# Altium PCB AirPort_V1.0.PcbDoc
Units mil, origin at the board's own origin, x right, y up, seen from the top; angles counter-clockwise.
Board outline 2235 x 1330 mil, 2 copper layers (Top Layer, Bottom Layer); 46 components, 18 nets, 126 pads, 46 vias.
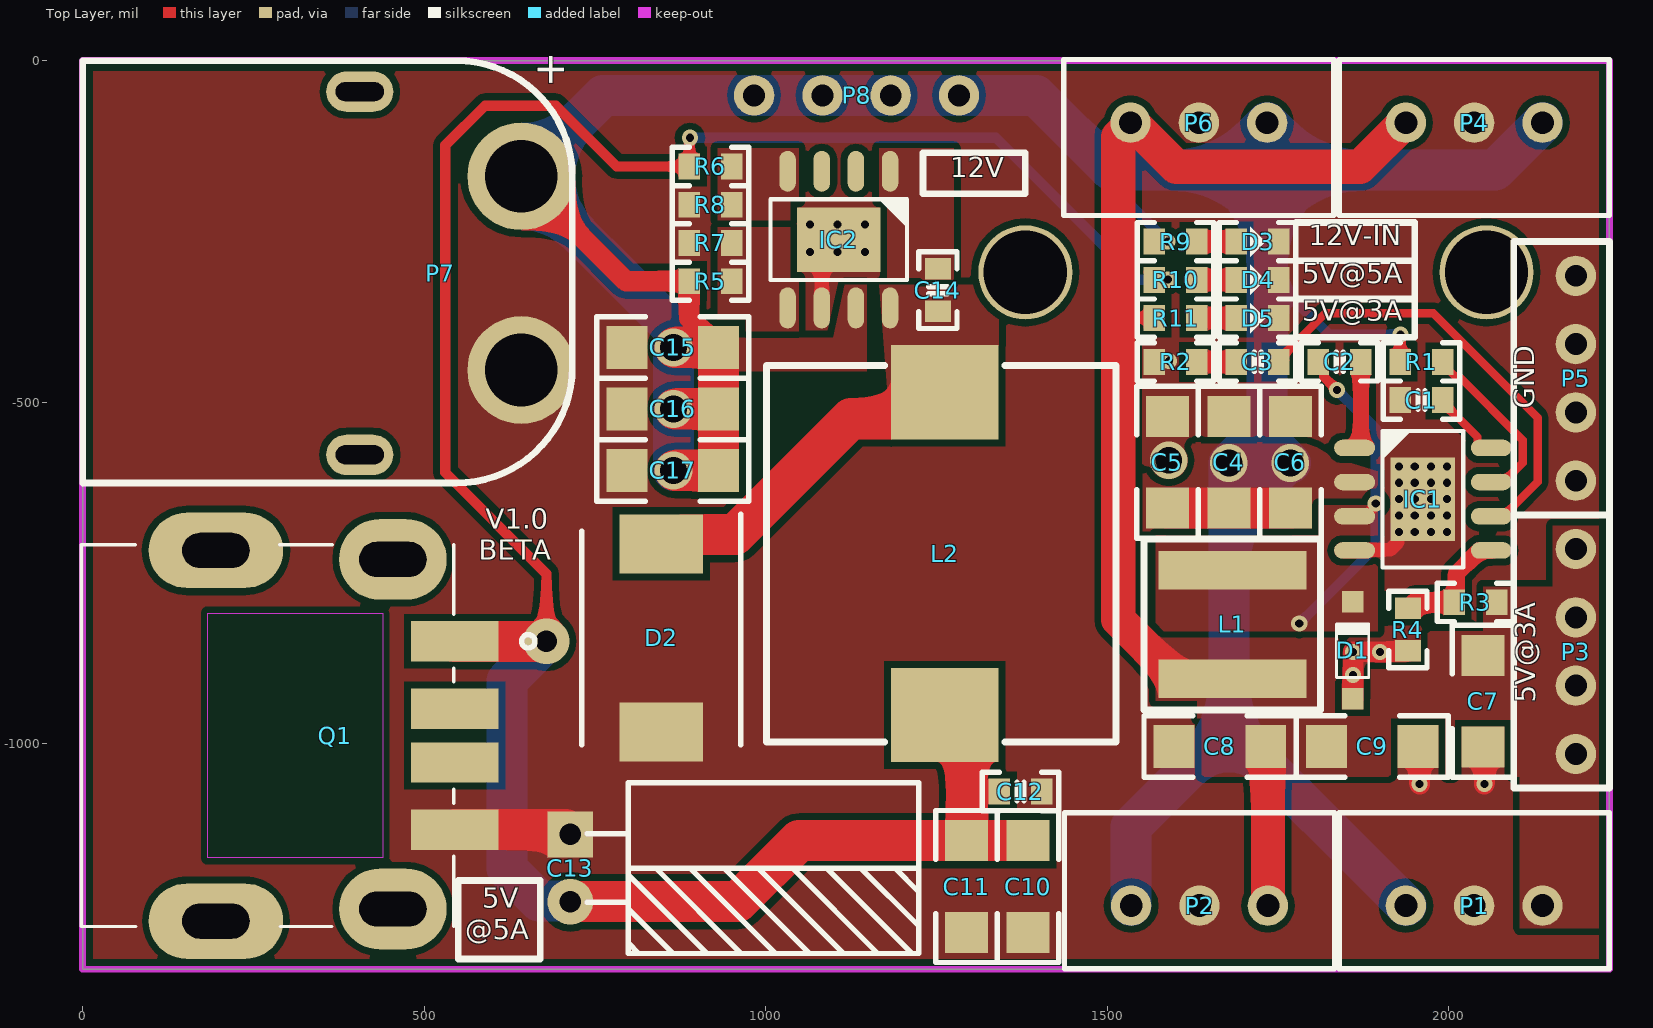
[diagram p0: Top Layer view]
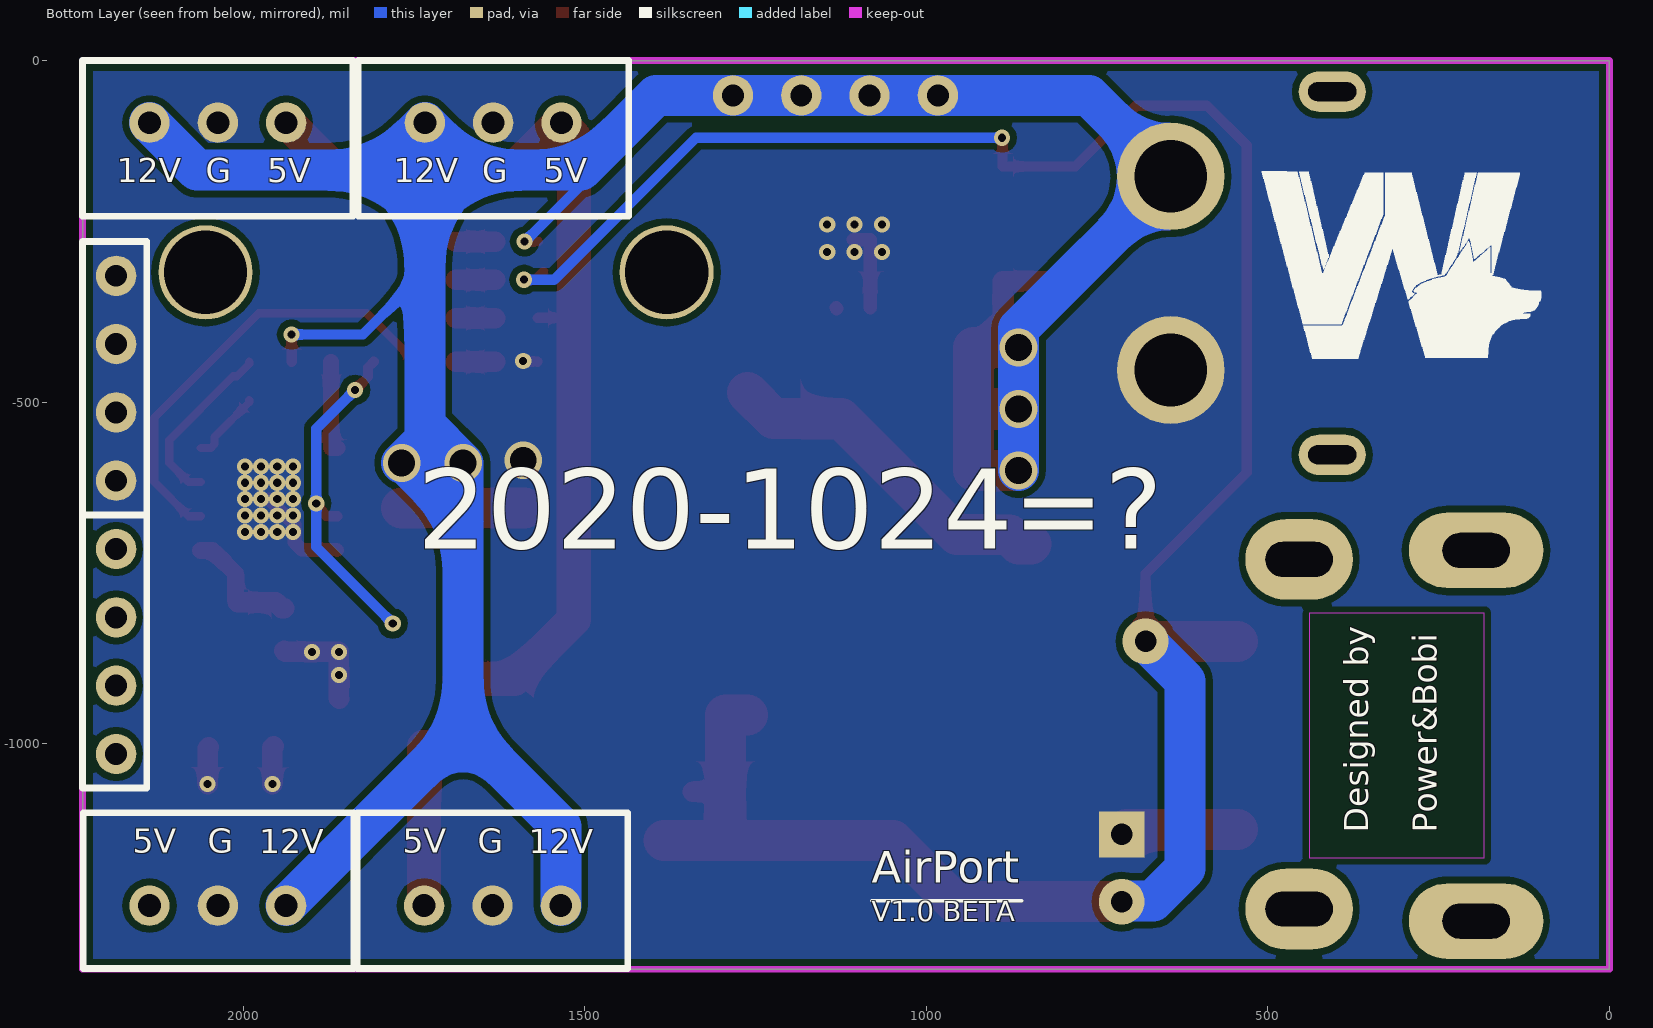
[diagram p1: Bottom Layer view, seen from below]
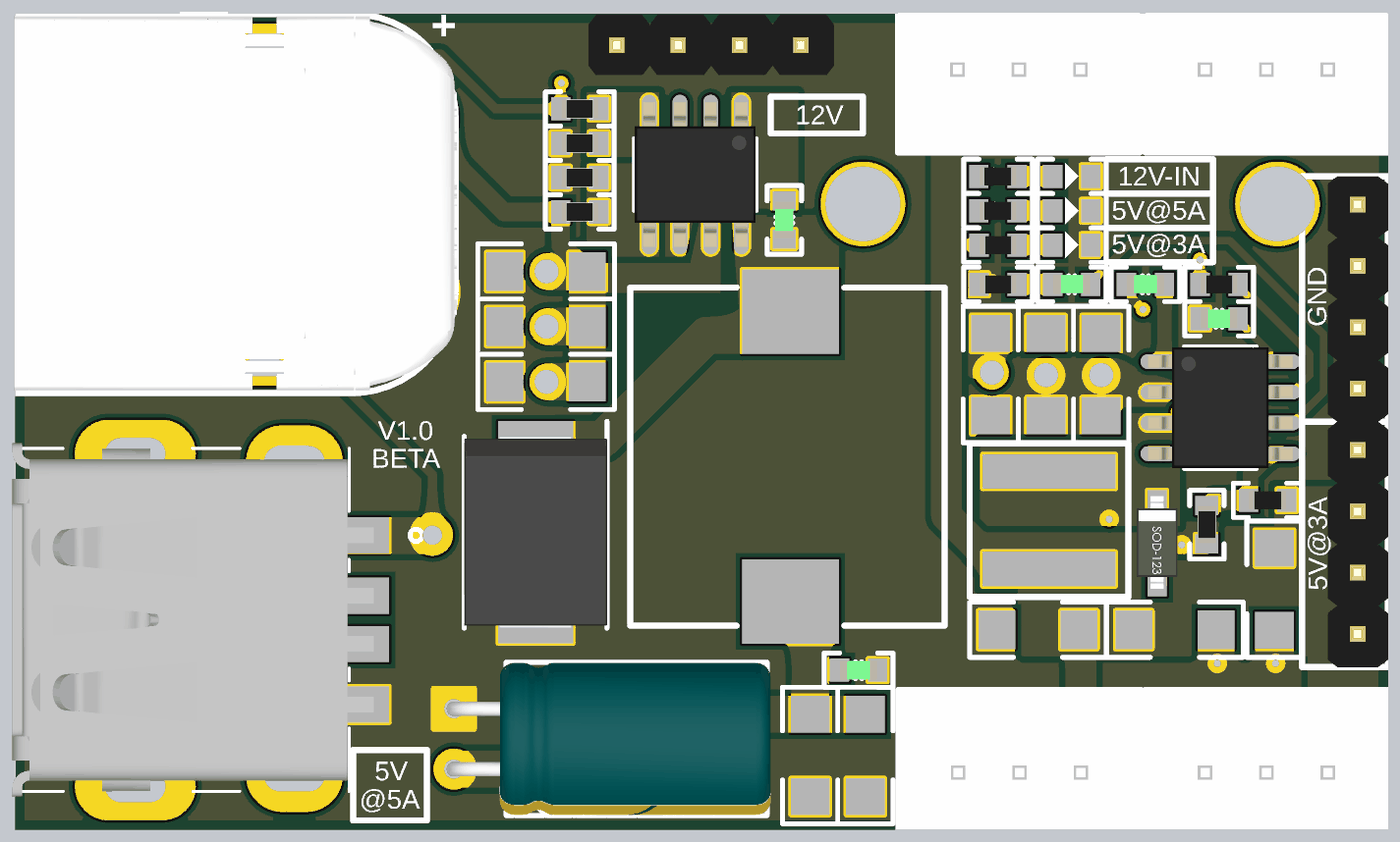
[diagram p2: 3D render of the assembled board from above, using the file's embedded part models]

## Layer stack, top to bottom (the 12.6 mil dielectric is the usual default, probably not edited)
Top Solder: solder mask 0.4, Solder Resist, Dk 3.5
Top Layer: signal copper 1.4
Dielectric 1: dielectric 12.6, FR-4, Dk 4.8
Bottom Layer: signal copper 1.4
Bottom Solder: solder mask 0.4, Solder Resist, Dk 3.5

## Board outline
0,-1330 0,0 2235,0 2235,-1330

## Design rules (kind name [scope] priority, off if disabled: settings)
Clearance [All] p1: gap=10 ignorepadtopadclearanceinfootprint=FALSE except(0: Arc-Hole Track-Hole SMDPad-Hole THPad-Hole Via-Hole Fill-Hole Poly-Hole Region-Hole Text-Hole)
PlaneConnect [All] p1: planeconnectstyle=Direct reliefexpansion=20 reliefentries=4 reliefconductorwidth=10 reliefairgap=10
PolygonConnect [All] p1: connectstyle=Direct reliefconductorwidth=10 reliefentries=4 polygonreliefangle="90 Angle" airgapwidth=10
RoutingVias [All] p1: holewidth=11.81 width=23.62 viastyle="Through Hole" minholewidth=11.81 minwidth=23.62 maxholewidth=11.81 maxwidth=23.62
SolderMaskExpansion [All] p1: expansion=4 istentingtop=FALSE
Width [All] p1: maxlimit=100 minlimit=10 preferedwidth=15
29 further rules are at their usual default settings.

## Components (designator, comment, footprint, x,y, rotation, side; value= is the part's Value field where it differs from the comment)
C1 "100nF" CAP-0603 1959.9,-497 r0 top
C2 "10nF" CAP-0603 1840,-441 r0 top
C3 "6.8nF" CAP-0603 1720,-441 r0 top
C4 "10uF" CAP-1206 1678,-588.07 r270 top
C5 "10uF" CAP-1206 1588,-588.07 r270 top
C6 "10uF" CAP-1206 1768,-588.07 r270 top
C7 "10uF" CAP-1206 2050,-937.93 r90 top
C8 "10uF" CAP-1206 1665,-1004 r0 top
C9 "10uF" CAP-1206 1887.93,-1004 r180 top
C10 "10uF" CAP-1206 1384,-1208.93 r90 top
C11 "10uF" CAP-1206 1294,-1208.93 r90 top
C12 "0.01uF" CAP-0603 1372.9,-1070 r180 top
C13 "100nF" "CAP-2.5*6.3*11.2-H - GD" 714,-1182 r270 top
C14 "0.01uF" CAP-0603 1252,-336.13 r90 top
C15 "4.7uF" CAP-1206 864,-420 r0 top
C16 "4.7uF" CAP-1206 864,-510 r0 top
C17 "0.01uF" CAP-1206 864,-600 r0 top
D1 "SS14" SOD_123 1859,-863 r270 top
D2 "SS14" DO-214AB 847,-845.2 r270 top
D3 "RED" LED-0603 1720,-265 r0 top
D4 "RED" LED-0603 1720.1,-321 r0 top
D5 "RED" LED-0603 1720,-377 r0 top
IC1 "MP1484" SOIC_8_PAD 1962,-642 r270 top
IC2 "TPS5450DDA" SOIC_8_PAD 1107,-262.06 r180 top
L1 "10uH 5A" XAL6060-103MEB 1683,-825.47 r90 top
L2 "15uH" SMD-13.45x12.6x4.8mm 1271.83,-720.78 r270 top
P1 "XH-3AW" XH_3 2037,-1237 r0 top
P2 "XH-3AW" XH_3 1635,-1237 r0 top
P3 "HDR1x4_2.54" HDR1x4_2.54_180 2185.82,-715 r0 top
P4 "XH-3AW" XH_3 2037,-91 r180 top
P5 "HDR1x4_2.54" HDR1x4_2.54_180 2185.82,-315 r0 top
P6 "XH-3AW" XH_3 1634,-91 r180 top
P7 "XT60PW-M" XT60PW-M 642,-453 r90 top
P8 "HDR1x4_2.54" HDR1x4_2.54_180 983,-51 r90 top
Q1 "USB A" USB_A_MALE_4_POS_Solder_RA_SMD_4_Terminal_1_Port 455.27,-988 r270 top
R1 "100K" R-0603 1959.9,-441 r180 top
R2 "6.8K" R-0603 1600,-441 r180 top
R3 "44.2K" R-0603 2038.9,-793 r0 top
R4 "10K" R-0603 1940,-832.9 r90 top
R5 "15K" R-0603 918.9,-323 r180 top
R6 "10K" R-0603 919,-155 r0 top
R7 "10K" R-0603 918.9,-267 r180 top
R8 "3.16K" R-0603 918.9,-211 r0 top
R9 "10k" R-0603 1599.9,-265 r180 top
R10 "10k" R-0603 1599.9,-321 r180 top
R11 "10k" R-0603 1600,-377 r180 top

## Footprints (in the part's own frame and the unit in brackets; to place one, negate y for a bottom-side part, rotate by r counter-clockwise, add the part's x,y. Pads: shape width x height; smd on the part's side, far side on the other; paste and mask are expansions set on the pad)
"CAP-2.5*6.3*11.2-H - GD" [mm] "脚距2.5mm直径6.3mm高度11.2mm"
  rect 1.7x1.7 hole 0.8: 1(-1.25,0)
  round 1.7 hole 0.8: 2(1.25,0)
  silkscreen extent -3.18,0.63 3.17,12.95, body extent -3.15,-0.3 3.16,13.11, height 6.32
CAP-0603 [mm]
  rect 0.8x0.96 smd: 1(-0.79,0) 2(0.79,0)
  silkscreen extent -1.42,-0.71 1.42,0.71, body extent -0.76,-0.39 0.76,0.39, height 0.9
CAP-1206 [mm] "贴片元件"
  rect 1.524x1.6 smd: 1(-1.703,0) 2(1.7,0)
  silkscreen extent -2.83,-1.14 2.83,1.14, body extent -1.91,-0.89 1.91,0.89, height 1
DO-214AB [mm]
  rect 2.2x3.1 smd: 1(3.5,0) 2(-3.5,0)
  silkscreen extent -4.6,-2.95 3.97,2.95, body extent -3.97,-2.95 3.97,2.95, height 2.5
HDR1x4_2.54_180 [mm]
  round 1.5 hole 0.813: 1(0,0) 2(0,-2.54) 3(0,-5.08) 4(0,-7.62)
  body extent -1.25,-8.89 1.25,1.27, height 8.2
LED-0603 [mm]
  rect 0.8x0.96 smd: 1(-0.79,0) 2(0.79,0)
  silkscreen extent -1.42,-0.71 1.42,0.71, body extent -0.81,-0.4 0.81,0.4, height 0.6
R-0603 [mm]
  rect 0.8x0.96 smd: 1(-0.79,0) 2(0.79,0)
  silkscreen extent -1.42,-0.71 1.42,0.71, body extent -0.76,-0.38 0.76,0.38, height 0.41
SMD-13.45x12.6x4.8mm [mm]
  rect 3.5x4 smd: 1(-5.975,-0.25) 2(6.025,-0.25)
  silkscreen extent -6.98,-6.88 7.03,6.12, body extent -6.96,-6.88 7.01,6.08, height 5
SOD_123 [mm]
  rect 0.8x0.8 smd: 1(1.8,0) 2(-1.8,0)
  silkscreen extent -1.02,-0.6 1.02,0.6, body extent -1.95,-0.85 1.9,0.85, height 1.42
SOIC_8_PAD [mil]
  oval 24x60 smd: 1(-75,-100) 2(-25,-100) 3(25,-100) 4(75,-100) 5(75,100) 6(25,100) 7(-25,100) 8(-75,100)
  rect 122.05x94.49 smd: 9(0,0)
  silkscreen extent -100,-59 100,59, body extent -98,-118 98,118, height 71
USB_A_MALE_4_POS_Solder_RA_SMD_4_Terminal_1_Port [mm] "能过5A大电流：https://item.taobao.com/item.htm?spm=a1z0d.6639537.1997196601.4.56bb7484TiP584&id=575662474806"
  rect 1.5x3.25 smd: 1(-3.5,2.27) 2(-1,2.27) 3(1,2.27) 4(3.5,2.27)
  oval 2.8x5 hole 1.3 slot 2.5 at 90 deg: ""(-6.883,-6.604) ""(6.9,-6.604)
  oval 3x4 hole 1.3 slot 2.5 at 90 deg: ""(-6.55,-0.025) ""(6.45,-0.025)
  Keep-Out Layer region: 4.55,-6.914 -4.553,-6.914 -4.553,-0.41 4.55,-0.41
  silkscreen extent -7.1,-11.61 7.1,5.26, body extent -7.32,-11.68 7.31,3.26, height 7.63
XAL6060-103MEB [mm]
  rect 1.43x5.5 smd: 1(-2.02,0) 2(2.02,0)
  silkscreen extent -3.18,-3.28 3.18,3.28, body extent -2.84,-2.84 2.84,2.84, height 2.03
XH_3 [mm]
  round 1.5 hole 0.85: 1(-2.54,0) 2(0,0) 3(2.54,0)
  silkscreen extent -5.02,-2.35 5.02,3.45, body extent -5.02,-2.35 5.02,3.45, height 7.21
XT60PW-M [mm]
  oval 1.5x2.5 hole 0.7 slot 1.8 at 90 deg: 0(-3.15,6) 0(10.35,6)
  round 4 hole 2.7: 1(7.2,0) 2(0,0)
  silkscreen extent -4.2,-1.9 11.5,16.3, body extent -4.3,-1.95 11.6,16.35, height 8.45

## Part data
C1 C2 C3 C4 C5 C6 C7 C8 C9 C10 C11 C12 C14 C15 C16 C17: library part CAP, "贴片电容", Package=0402, SuppliersPartNumber=C52923
C13: library part CAP-POL, "贴片电容-有极性", Package=3528, SuppliersPartNumber=C16133
D1 D2: library part DIODE, "二极管", Package=SMA(DO-214AC), SuppliersPartNumber=C22452
D3 D4 D5: library part LED, "发光二极管", Package=0603, SuppliersPartNumber=C2290
IC1: "同步降压稳压器", Manufacturer_Name="Monolithic Power Systems (MPS)", Manufacturer_Part_Number=MP1484EN-LF, Mouser Part Number=946-MP1484ENLF
IC2: "集成稳压芯片", Manufacturer_Name="Texas Instruments", Mouser Part Number=595-TPS5450DDA
L1: library part INDUCTOR, "贴片电感", Package=0402, SuppliersPartNumber=C32041
L2: library part INDUCTOR, "8A 贴片电感CMKD-1350A-150M", Package=0402, SuppliersPartNumber=C32041
P1 P2 P4 P6: library part HDR1x3_2.54, "Header"
P3 P5 P8: "Header"
P7: library part XT60, "XT60"
Q1: "USB 接口"
R1 R2 R3 R4 R5 R6 R7 R8 R9 R10 R11: library part RES, "贴片电阻", Package=0805, SuppliersPartNumber=C17798

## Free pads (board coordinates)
  round 137.8 hole 122.05: 2(1380,-310) 2(2055,-310)

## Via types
v1: diameter 23.62, hole 11.81, Top Layer to Bottom Layer, 39 vias
v2: diameter 55.12, hole 39.37, Top Layer to Bottom Layer, 6 vias
v3: diameter 66.93, hole 31.5, Top Layer to Bottom Layer, 1 vias

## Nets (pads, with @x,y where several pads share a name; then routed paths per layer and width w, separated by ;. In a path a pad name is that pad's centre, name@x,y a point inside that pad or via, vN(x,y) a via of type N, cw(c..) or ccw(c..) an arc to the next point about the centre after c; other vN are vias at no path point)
5V@3A: C7.2 C8.2 C9.2 L1.1 P1.3 P2.3 P3.1 P3.2 P3.3 P3.4 P4.3 P6.3 R3.2 R11.2 | length 1677.4
  Top Layer w15: 1522,-376 1522.5,-376.5 1568.4,-376.5 R11.2
  Top Layer w50: L1.1 1602.88,-905 1516,-818.12 1516,-111.45 1534,-93.45 P6.3 1536.45,-91 1600.98,-155.53 1870.02,-155.53 1934.55,-91 P4.3 ; C8.2 1735,-1004 P2.3
5V@5A: C10.2 C11.2 C12.2 C13.2 L2.2 Q1.1 R6.1 R10.2 | length 3665.8
  Top Layer w15: v3(679,-850) 679,-751 531,-603 531,-124 589,-66 692.75,-66 781.75,-155 R6.1 ; v1(889,-113) 888.45,-113.55 R6.1@888.45,-151.3 ; R10.2@1560.55,-309.65 1568.8,-317.9 R10.2 1569.3,-321.5 1589.5,-321.5 1588.75,-320.75 v1(1588.62,-320.75) 1574.06,-320.75 R10.2@1572.81,-322 ; R6.1 888.45,-154.45 R6.1@888.45,-151.3 ; R6.1 887.9,-151.85 R6.1@888.45,-151.3
  Top Layer w30: 1294,-1070 C12.2
  Top Layer w60: Q1.1 545.11,-850.68 678.32,-850.68 v3(679,-850) ; C13.2 959.58,-1231.21 1048.8,-1142 C11.2 ; L2.2 1294,-958 1294,-1070 C11.2 ; C10.2 C11.2
  Bottom Layer w15: v1(889,-113) 1337,-113 1544.75,-320.75 v1(1588.62,-320.75)
  Bottom Layer w60: v3(679,-850) 621,-908 621,-1182.74 668.15,-1229.89 712.67,-1229.89 C13.2
12V: C4.2 C5.2 C6.2 C15.2 C16.2 C17.2 IC1.2 IC2.7 P1.1 P2.1 P4.1 P6.1 P7.1 P8.1 P8.2 P8.3 P8.4 R1.2 R5.2 R9.2 | length 5802.7
  Top Layer w15: R9.2 v1(1588,-265) ; R1.2 1928.8,-401 v1(1929,-401)
  Top Layer w20: C15.2 C15.2@935.93,-425 ; IC2.7@1131.23,-362.83 IC2.7
  Top Layer w30: P7.1 795.46,-323 R5.2 887.8,-376.87 C15.2@914.43,-403.5
  Top Layer w60: v2@866.95,-600 C17.2 C16.2 ; v2@866.95,-510 C16.2 ; v2@866.95,-420 C15.2 C16.2 ; C5.2 C4.2 C6.2
  Bottom Layer w15: 1505.2,-160.53 1505.2,-182.2 v1(1588,-265) ; 1734,-310 1825,-401 v1(1929,-401)
  Bottom Layer w60: v2(865,-599.98) v2(865,-510) v2(865,-419.98) 865,-392.54 P7.1 643.56,-169.54 762.1,-51 P8.1 P8.2 P8.3 P8.4 1395.67,-51 1505.2,-160.53 1664.47,-160.53 ; P2.1 1535,-1121 1678,-978 ; P1.1 1678,-978 ; P4.1 2067.47,-160.53 1803.53,-160.53 ; 1664.47,-160.53 1734,-230.06 ; 1664.47,-160.53 1734,-160.53 ; 1664.47,-160.53 P6.1 ; 1678,-978 1678,-675 ; 1678,-675 v2(1678,-589) ; 1678,-675 v2@1764,-589 ; v2(1678,-589) v2@1764,-589 ; v2(1678,-589) 1734,-533 ; 1734,-533 1734,-310 1734,-230.06 ; 1734,-533 1734,-555 v2(1768,-589) v2@1764,-589 ; 1734,-230.06 1803.53,-160.53 ; 1734,-230.06 1734,-160.53 ; 1734,-160.53 P6.1 ; 1734,-160.53 1803.53,-160.53 ; P6.1 1803.53,-160.53
GND: C1.1 C4.1 C5.1 C6.1 C7.1 C8.1 C9.1 C10.1 C11.1 C12.1 C13.1 C15.1 C16.1 C17.1 D1.1 D2.1 D3.2 D4.2 D5.2 IC1.4 IC1.9 IC2.6 IC2.9 P1.2 P2.2 P4.2 P5.1 P5.2 P5.3 P5.4 P6.2 P7.2 Q1.4 R2.2 R4.1 R7.2 R8.1 | length 725.2
  Top Layer w15: R2.2 1569.4,-440.5 1589.5,-440.5 v1(1590,-440)
  Top Layer w20: IC2.6 1082,-262.06 IC2.9 ; IC1.4 1862.77,-716.23 1913.77,-716.23 1924.76,-705.24 1924.76,-679.24 IC1.9
  Top Layer w30: D1.1 1859.77,-933.1 v1(1859.77,-865.63) 1938.37,-865.63 R4.1 ; C9.1 1957,-1006.02 v1(1957,-1059) ; C7.1 2052,-1006.98 v1(2052,-1059)
  Top Layer w60: Q1.4 707.01,-1125.8 C13.1
  other v1: 1859.77,-899.36 1899.07,-865.63 1927,-690 1950,-690 1974,-690 1997,-690 1927,-666 1950,-666 1974,-666 1997,-666 1927,-642 1950,-642 1974,-642 1997,-642 1927,-618 1950,-618 1974,-618 1997,-618 1927,-594 1950,-594 1974,-594 1997,-594 1065,-280 1105,-280 1145,-280 1065,-240 1105,-240 1145,-240
  other v2: 1590,-585
NetC1_2: C1.2 IC1.8 | length 108.1
  Top Layer w12: C1.2 1991,-500.15 2041.7,-550.85 2041.7,-561.46 2047.25,-567 IC1.8
NetC2_1: C2.1 D1.2 IC1.3 L1.2 | length 504.9
  Top Layer w15: C2.1 1817.15,-449.25 1817.15,-463.15 v1(1836,-482) ; IC1.3 1877.56,-667 1891.3,-653.27 1891.3,-649.88 v1(1892.94,-648.23)
  Bottom Layer w15: v1(1781,-824) 1892.94,-712.06 v1(1892.94,-648.23) 1892.94,-538.94 v1(1836,-482)
NetC2_2: C2.2 IC1.1 | length 135
  Top Layer w23.62: IC1.1 1870.93,-567 1871.1,-566.83 C2.2
NetC3_1: C3.1 R2.1 | length 57.8
  Top Layer w30: R2.1 C3.1
NetC3_2: C3.2 IC1.6 | length 656.4
  Top Layer w12: C3.2 1751.1,-437.85 1818.95,-370 1977.27,-370 2130,-522.73 2130,-617 2080,-667 IC1.6
NetC14_1: C14.1 D2.2 IC2.8 L2.1 | length 506.9
  Top Layer w60: D2.2 864.72,-707.41 878.02,-694.1 913.07,-694.1 913.17,-694 954.99,-694 1124.99,-524 1223.56,-524 L2.1
NetC14_2: C14.2 IC2.1
NetD3_A: D3.1 R9.1 | length 57.9
  Top Layer w30: R9.1 D3.1
NetD4_A: D4.1 R10.1 | length 58
  Top Layer w30: R10.1 D4.1
NetD5_A: D5.1 R11.1 | length 57.8
  Top Layer w30: R11.1 D5.1
NetIC1_5: IC1.5 R3.1 R4.2 | length 179.8
  Top Layer w25: R3.1 2011.04,-789.75 2011.04,-750.96 2045,-717 IC1.5
  Top Layer w30: R4.2 1943.15,-801.8 1951.94,-793 R3.1
NetIC1_7: IC1.7 R1.1 | length 257.4
  Top Layer w12: R1.1 1991,-444.15 2008.95,-462.1 2014.7,-462.1 2108,-555.4 2108,-589 2080,-617 IC1.7
NetIC2_4: IC2.4 R6.2 R8.2
NetIC2_5: IC2.5 R5.1 R7.1
pads on no net: IC2.2 IC2.3 P7.0 Q1. Q1.2 Q1.3

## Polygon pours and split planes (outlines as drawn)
GND on Top Layer "GND_L01_P033" (solid, remove dead copper, pour order 33): -175,120 -175,-1450 2455,-1450 2455,125
12V on Top Layer "12V_L01_P032" (solid, pour order 32): 1116,-328 1148,-328 1148,-455 901.11,-455 901.11,-406 1099,-406
12V on Top Layer "12V_L01_P031" (solid, pour order 31): 1804,-689 1896,-625 1896,-601 1827,-580 ccw(c1771.65,-641.92) 1767,-559 1552,-559 1552,-689
GND on Top Layer "GND_L01_P030" (solid, pour order 30): 1804,-689
NetC14_2 on Top Layer "NETC14_2_L01_P028" (solid, pour order 28): 1166,-128 1274.93,-128 1274.93,-324.54 1166,-324.54
NetC14_1 on Top Layer "NETC14_1_L01_P027" (solid, pour order 27): 1166,-328 1341,-328 1341,-417.22 1184,-555
NetIC2_4 on Top Layer "NETIC2_4_L01_P026" (solid, pour order 26): 930,-128 930,-234 1048,-234 1048,-128
NetIC2_5 on Top Layer "NETIC2_5_L01_P025" (solid, pour order 25): 930,-244 1048,-244 1048,-396 930,-396
5V@3A on Top Layer "5V@3A_L01_P023" (solid, pour order 23): 2219,-1048 2219,-1270 2104,-1270 2104,-1048
5V@3A on Top Layer "5V@3A_L01_P022" (solid, remove dead copper, pour order 22): 1571,-835 2050,-835 2050,-770 2152,-770 2152,-681 2219,-681 2219,-1048 1632,-1048 1632,-937 1571,-937
NetC2_1 on Top Layer "NETC2_1_L01_P021" (solid, pour order 21): 1896,-651 1571,-651 1571,-835 1896,-835
GND on Top Layer "NONET_L01_P020" (solid, remove dead copper, shelved, pour order 20): -2841,-2054.2 -2832,-2045.2 -2170,-2045.2 -2170,-2584.2 -2155,-2599.2 -2498,-2599.2 -2498,-2374 -2616.8,-2255.2 -2842.56,-2255.2
no net on Top Layer "NONET_L01_P019" (solid, shelved, pour order 19): -2889,-2155
NetC2_1 on Top Layer "NONET_L01_P018" (solid, shelved, pour order 18): -2531.77,-2459.01 -2756.27,-2459.01 -2756.27,-2324.8 -2531.73,-2324.8 -2531.73,-2458.94
no net on Top Layer "NONET_L01_P001" (solid, shelved, pour order 1): -2757,-2483
5V@3A on Top Layer "NONET_L01_P002" (solid, remove dead copper, shelved, pour order 2): -2757,-2483 -2757,-2557 -2319,-2557 -2319,-2399 -2422,-2399 -2422,-2483
NetIC1_5 on Top Layer "NONET_L01_P004" (solid, shelved, pour order 4): -2447,-2247 -2319,-2247 -2319,-2377 -2447,-2377
NetC3_2 on Top Layer "NONET_L01_P005" (solid, shelved, pour order 5): -2447,-2250 -2319,-2250 -2319,-2197 -2447,-2197
NetIC1_7 on Top Layer "NONET_L01_P006" (solid, shelved, pour order 6): -2447,-2194 -2319,-2194 -2319,-2147 -2447,-2147
NetC1_2 on Top Layer "NONET_L01_P007" (solid, shelved, pour order 7): -2447,-2138 -2319,-2138 -2319,-2092 -2447,-2092
NetC2_1 on Top Layer "NONET_L01_P008" (solid, shelved, pour order 8): -2757,-2285 -2757,-2388 -2458,-2388 -2458,-2285
12V on Top Layer "NONET_L01_P010" (solid, shelved, pour order 10): -2707,-2249 -2707,-2091 -2579,-2091 -2579,-2249
no net on Top Layer "NONET_L01_P015" (solid, shelved, pour order 15): -2757,-2552.71
5V@3A on Top Layer "NONET_L01_P017" (solid, shelved, pour order 17): -2531.73,-2548.13 -2756.27,-2548.2 -2756.27,-2439 -2531.73,-2439
GND on Bottom Layer "GND_L02_P034" (solid, remove dead copper, pour order 34): -185,150 -185,-1470 2430,-1470 2430,110
NetC2_1 on Bottom Layer "NONET_L02_P009" (solid, shelved, pour order 9): -2462,-2222 -2462,-2306 -2667,-2306 -2667,-2222
GND on Bottom Layer "NONET_L02_P012" (solid, remove dead copper, shelved, pour order 12): -2870,-2010 -2870,-2609 -2056,-2609 -2056,-2010

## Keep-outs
Keep-Out Layer:
  lines w10: -2812.06,-2568 5220,-2568 5220,2417 -2812.06,2417 -2812.06,-2568 ; 0,-1330 2235,-1330 2235,0 0,0 0,-1330

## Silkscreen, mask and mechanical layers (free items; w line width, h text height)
Top Overlay:
  lines w10: 1776,-405 1950,-405 1950,-237 1776,-237 ; 1776,-349 1950,-349 1950,-293 1776,-293 ; 2095,-665 2095,-265 2235,-265 2235,-665 ; 2095,-665 2095,-1065 2235,-1065 2235,-665 ; 2095,-665 2105,-665 2235,-665 ; 550,-1315 670,-1315 670,-1200 550,-1200 550,-1315 ; 1230,-195 1380,-195 1380,-135 1230,-135 1230,-195
  text "12V" at 1270,-180 h50
  text "12V-IN" at 1795,-280 h50
  text "5V@5A" at 1785,-335.6 h50
  text "5V@3A" at 1785,-390.6 h50
  text "GND" at 2134.48,-510 h50 r90
  text "V1.0" at 590.03,-694.48 h50
  text "BETA" at 580,-740 h50
  text "5V@3A" at 2135.6,-940 h50 r90
  text "5V" at 585,-1249.48 h50
  text "@5A" at 560,-1295.6 h50
Bottom Overlay:
  drawing of 1762 lines, arcs and shapes, not listed
  text "5V" at 1559.66,-189.63 h60
  text "G" at 1649.66,-189.96 h60
  text "12V" at 1779.66,-190 h60
  text "5V" at 1965,-189.63 h60
  text "G" at 2055,-189.96 h60
  text "12V" at 2185,-190 h60
  text "2020-1024=?" at 1745.14,-752.92 h200
  text "Power&Bobi" at 240.87,-1130 h60 r270
  text "Designed by" at 341.27,-1130 h60 r270
  text "12V" at 1581.55,-1172.25 h60
  text "G" at 1656.55,-1171.63 h60
  text "5V" at 1766.55,-1171.63 h60
  text "12V" at 1976.55,-1172.25 h60
  text "G" at 2051.55,-1171.63 h60
  text "5V" at 2161.55,-1171.63 h60
  text "AirPort" at 1080,-1219.17 h80
  text "V1.0 BETA" at 1079.97,-1269.48 h50
Mechanical 1:
  the board outline again, w10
